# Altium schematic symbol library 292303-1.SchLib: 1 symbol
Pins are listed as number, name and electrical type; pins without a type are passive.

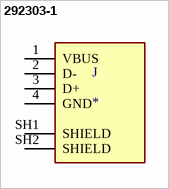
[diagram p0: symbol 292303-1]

## 292303-1
designator J
Conn; Data; USB; Recept; 2.0; 4 Pos; 1 Port; Rt Angle; A Ser; Tin over Copper; Number_of_Positions: 4; MP: 292303-1; Centerline_Pitch: 2 mm[.078 in]; MF: TE Connectivity; Product_Type: Connector
footprint TE_292303-1
pins: 1 VBUS, 2 D-, 3 D+, 4 GND, SH1 SHIELD, SH2 SHIELD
